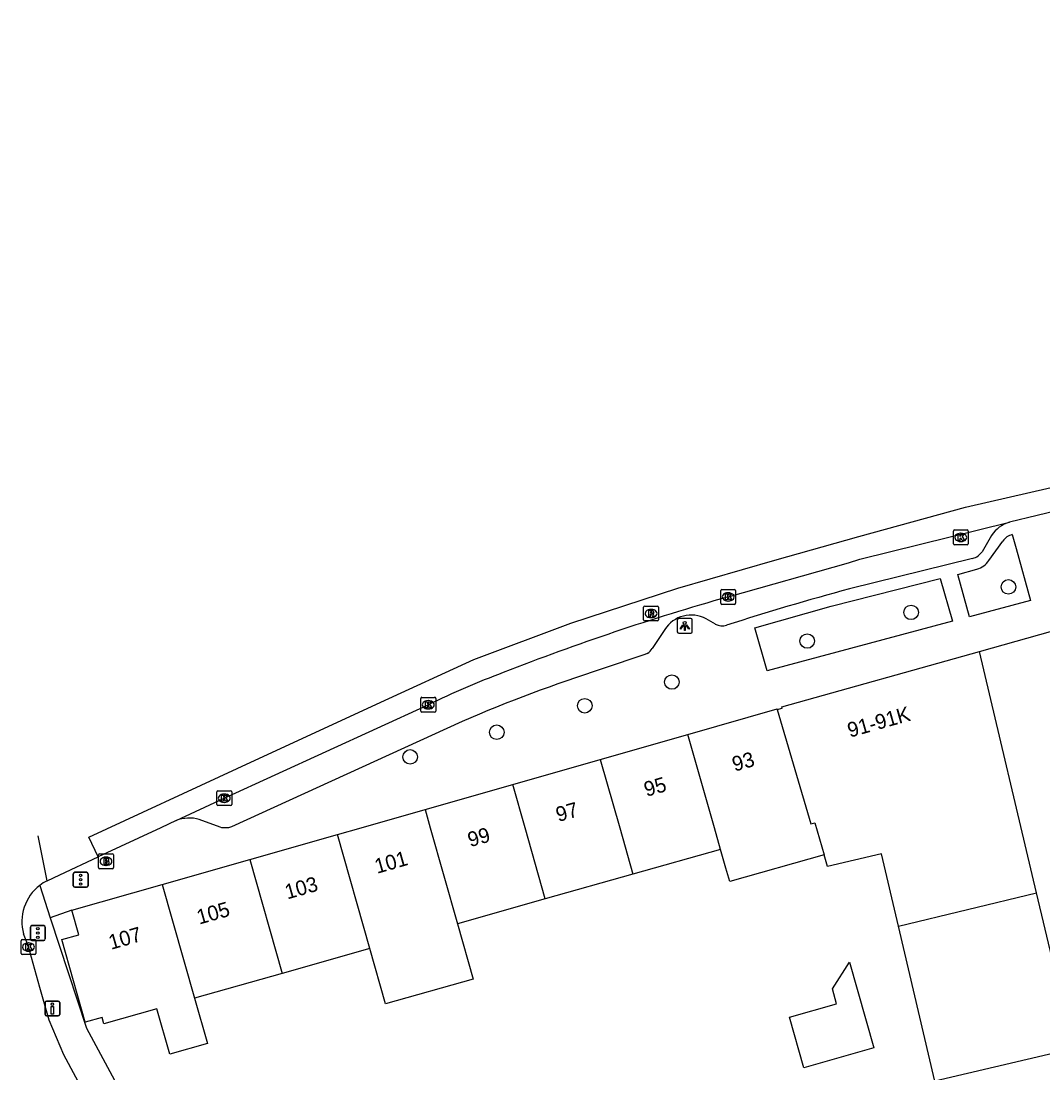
# Model space of a CAD drawing. Extents: x 159053 to 160041, y 380450 to 381422.
# Drawn here: x 159235.3 to 159304.1, y 381233.5 to 381304.3 of the extents above; entities that cross this region are included whole.
import ezdxf

# ---------------------------------------------------------------- set-up
doc = ezdxf.new("R2010")
doc.units = 0
for name, color, linetype in [('IMGEO_Boom', 7, 'Continuous'), ('IMGEO_Brandkraan', 7, 'Continuous'), ('IMGEO_Drukknoppaal', 7, 'Continuous'), ('IMGEO_Kolk', 7, 'Continuous'), ('IMGEO_Lichtpunt', 7, 'Continuous'), ('IMGEO_Muur', 7, 'Continuous'), ('IMGEO_Pand', 7, 'Continuous'), ('IMGEO_Pand_nummerreeks', 7, 'Continuous'), ('IMGEO_Rijbaan_lokaal_gesloten', 7, 'Continuous'), ('IMGEO_Rioolput', 7, 'Continuous'), ('IMGEO_Verkeersregelinstallatiepaal', 7, 'Continuous'), ('IMGEO_Voetpad_open', 7, 'Continuous')]:
    doc.layers.add(name, color=color, linetype=linetype)

msp = doc.modelspace()

# ---------------------------------------------------------------- linework, layer by layer
at = {"layer": 'IMGEO_Boom'}
for centre in [(159301.757, 381266.198), (159295.21, 381264.485), (159288.216, 381262.556), (159279.111, 381259.798), (159273.253, 381258.203), (159267.332, 381256.422), (159261.504, 381254.761)]:
    msp.add_circle(centre, 0.489, dxfattribs=at)
at = {"layer": 'IMGEO_Brandkraan'}
for p, q in [((159240.539, 381247.312), (159240.539, 381248.164)), ((159240.614, 381248.238), (159241.466, 381248.238)), ((159241.54, 381248.164), (159241.54, 381247.312)), ((159241.05, 381247.458), (159241.025, 381247.458)), ((159241.027, 381248.018), (159241.052, 381248.018)), ((159241.466, 381247.238), (159240.614, 381247.238))]:
    msp.add_line(p, q, dxfattribs=at)
for points in [[(159240.539, 381247.312), (159240.539, 381248.164)], [(159240.614, 381248.238), (159241.466, 381248.238)], [(159241.54, 381248.164), (159241.54, 381247.312)], [(159240.887, 381247.938), (159240.887, 381247.538), (159241.1, 381247.538)], [(159241.118, 381247.938), (159240.887, 381247.938)], [(159241.066, 381247.857), (159241.012, 381247.857), (159241.012, 381247.781)], [(159241.012, 381247.781), (159241.065, 381247.781)], [(159241.074, 381247.705), (159241.012, 381247.705), (159241.012, 381247.624)], [(159241.012, 381247.624), (159241.074, 381247.624)], [(159241.466, 381247.238), (159240.614, 381247.238)]]:
    msp.add_lwpolyline(points, dxfattribs=at)
for centre, radius, start, end in [((159240.616, 381248.162), 0.0765, 91.55205, 178.44795), ((159240.616, 381248.162), 0.0765, 91.55205, 178.44795), ((159241.464, 381248.162), 0.0765, 1.55205, 88.44795), ((159241.464, 381248.162), 0.0765, 1.55205, 88.44795), ((159241.067, 381247.819), 0.0379, 267.82845, 90.93552), ((159241.075, 381247.664), 0.0404, 269.87594, 90.50774), ((159241.106, 381247.789), 0.251, 268.66757, 293.53466), ((159241.122, 381247.793), 0.145, 59.4692, 91.53667), ((159241.147, 381247.84), 0.0922, 285.51372, 58.15012), ((159241.152, 381247.648), 0.105, 301.31148, 78.98903), ((159240.616, 381247.314), 0.0765, 181.55205, 268.44795), ((159240.616, 381247.314), 0.0765, 181.55205, 268.44795), ((159241.464, 381247.314), 0.0765, 271.55205, 358.44795), ((159241.464, 381247.314), 0.0765, 271.55205, 358.44795)]:
    msp.add_arc(centre, radius, start, end, dxfattribs=at)
for centre, major_axis, ratio, start_param, end_param in [((159241.026, 381247.738), (-0.387, 0.002), 0.722429, 4.712389, 7.853982), ((159241.051, 381247.738), (-0.39, 0.002), 0.717154, 1.570796, 4.712389)]:
    msp.add_ellipse(centre, major_axis=major_axis, ratio=ratio, start_param=start_param, end_param=end_param, dxfattribs=at)
at = {"layer": 'IMGEO_Drukknoppaal'}
for p, q in [((159237.036, 381238.339), (159237.826, 381238.339)), ((159237.826, 381238.339), (159237.036, 381238.339)), ((159236.936, 381237.439), (159236.936, 381238.239)), ((159236.936, 381238.239), (159236.936, 381237.439)), ((159237.926, 381238.239), (159237.926, 381237.439)), ((159237.926, 381237.439), (159237.926, 381238.239)), ((159237.826, 381237.339), (159237.036, 381237.339)), ((159237.036, 381237.339), (159237.826, 381237.339))]:
    msp.add_line(p, q, dxfattribs=at)
msp.add_lwpolyline([(159237.506, 381237.964), (159237.506, 381237.464), (159237.356, 381237.464), (159237.356, 381237.964), (159237.506, 381237.964)], dxfattribs=at)
msp.add_circle((159237.431, 381238.129), 0.085, dxfattribs=at)
for centre, start, end in [((159237.036, 381238.239), 90, 180), ((159237.036, 381238.239), 90, 180), ((159237.826, 381238.239), 0, 90), ((159237.826, 381238.239), 360, 90), ((159237.036, 381237.439), 180, 270), ((159237.036, 381237.439), 180, 270), ((159237.826, 381237.439), 270, 0), ((159237.826, 381237.439), 270, 0)]:
    msp.add_arc(centre, 0.1, start, end, dxfattribs=at)
at = {"layer": 'IMGEO_Kolk'}
for p, q in [((159298.05, 381269.104), (159298.05, 381269.956)), ((159298.125, 381270.03), (159298.977, 381270.03)), ((159298.538, 381269.81), (159298.563, 381269.81)), ((159299.051, 381269.956), (159299.051, 381269.104)), ((159298.977, 381269.03), (159298.125, 381269.03)), ((159298.561, 381269.25), (159298.536, 381269.25)), ((159282.403, 381265.098), (159282.403, 381265.95)), ((159282.478, 381266.024), (159283.33, 381266.024)), ((159283.404, 381265.95), (159283.404, 381265.098)), ((159282.914, 381265.244), (159282.889, 381265.244)), ((159282.891, 381265.804), (159282.916, 381265.804)), ((159283.33, 381265.024), (159282.478, 381265.024)), ((159262.298, 381258.769), (159263.15, 381258.769)), ((159262.223, 381257.843), (159262.223, 381258.695)), ((159262.711, 381258.549), (159262.736, 381258.549)), ((159263.224, 381258.695), (159263.224, 381257.843)), ((159263.15, 381257.769), (159262.298, 381257.769)), ((159262.734, 381257.989), (159262.709, 381257.989)), ((159248.497, 381251.559), (159248.497, 381252.411)), ((159248.572, 381252.485), (159249.424, 381252.485)), ((159249.498, 381252.411), (159249.498, 381251.559)), ((159249.008, 381251.705), (159248.983, 381251.705)), ((159248.985, 381252.265), (159249.01, 381252.265)), ((159249.424, 381251.485), (159248.572, 381251.485)), ((159235.323, 381241.544), (159235.323, 381242.396)), ((159235.398, 381242.47), (159236.25, 381242.47)), ((159235.811, 381242.25), (159235.836, 381242.25)), ((159236.324, 381242.396), (159236.324, 381241.544)), ((159236.25, 381241.47), (159235.398, 381241.47)), ((159235.834, 381241.69), (159235.809, 381241.69))]:
    msp.add_line(p, q, dxfattribs=at)
for points in [[(159298.05, 381269.104), (159298.05, 381269.956)], [(159298.125, 381270.03), (159298.977, 381270.03)], [(159298.371, 381269.73), (159298.494, 381269.73), (159298.494, 381269.579), (159298.624, 381269.73), (159298.788, 381269.73), (159298.642, 381269.579), (159298.795, 381269.33), (159298.643, 381269.33), (159298.558, 381269.494), (159298.494, 381269.427), (159298.494, 381269.33), (159298.371, 381269.33), (159298.371, 381269.73)], [(159299.051, 381269.956), (159299.051, 381269.104)], [(159298.977, 381269.03), (159298.125, 381269.03)], [(159282.403, 381265.098), (159282.403, 381265.95)], [(159282.478, 381266.024), (159283.33, 381266.024)], [(159283.404, 381265.95), (159283.404, 381265.098)], [(159282.724, 381265.724), (159282.847, 381265.724), (159282.847, 381265.573), (159282.977, 381265.724), (159283.141, 381265.724), (159282.995, 381265.573), (159283.148, 381265.324), (159282.996, 381265.324), (159282.911, 381265.488), (159282.847, 381265.421), (159282.847, 381265.324), (159282.724, 381265.324), (159282.724, 381265.724)], [(159283.33, 381265.024), (159282.478, 381265.024)], [(159262.298, 381258.769), (159263.15, 381258.769)], [(159262.223, 381257.843), (159262.223, 381258.695)], [(159262.544, 381258.469), (159262.667, 381258.469), (159262.667, 381258.318), (159262.797, 381258.469), (159262.961, 381258.469), (159262.815, 381258.318), (159262.968, 381258.069), (159262.816, 381258.069), (159262.731, 381258.233), (159262.667, 381258.166), (159262.667, 381258.069), (159262.544, 381258.069), (159262.544, 381258.469)], [(159263.224, 381258.695), (159263.224, 381257.843)], [(159263.15, 381257.769), (159262.298, 381257.769)], [(159248.497, 381251.559), (159248.497, 381252.411)], [(159248.572, 381252.485), (159249.424, 381252.485)], [(159249.498, 381252.411), (159249.498, 381251.559)], [(159248.818, 381252.185), (159248.941, 381252.185), (159248.941, 381252.034), (159249.071, 381252.185), (159249.235, 381252.185), (159249.089, 381252.034), (159249.242, 381251.785), (159249.09, 381251.785), (159249.005, 381251.949), (159248.941, 381251.882), (159248.941, 381251.785), (159248.818, 381251.785), (159248.818, 381252.185)], [(159249.424, 381251.485), (159248.572, 381251.485)], [(159235.323, 381241.544), (159235.323, 381242.396)], [(159235.398, 381242.47), (159236.25, 381242.47)], [(159235.644, 381242.17), (159235.767, 381242.17), (159235.767, 381242.019), (159235.897, 381242.17), (159236.061, 381242.17), (159235.915, 381242.019), (159236.068, 381241.77), (159235.916, 381241.77), (159235.831, 381241.934), (159235.767, 381241.867), (159235.767, 381241.77), (159235.644, 381241.77), (159235.644, 381242.17)], [(159236.324, 381242.396), (159236.324, 381241.544)], [(159236.25, 381241.47), (159235.398, 381241.47)]]:
    msp.add_lwpolyline(points, dxfattribs=at)
for centre, start, end in [((159298.127, 381269.954), 91.55205, 178.44795), ((159298.127, 381269.954), 91.55205, 178.44795), ((159298.975, 381269.954), 1.55205, 88.44795), ((159298.975, 381269.954), 1.55205, 88.44795), ((159298.127, 381269.106), 181.55205, 268.44795), ((159298.127, 381269.106), 181.55205, 268.44795), ((159298.975, 381269.106), 271.55205, 358.44795), ((159298.975, 381269.106), 271.55205, 358.44795), ((159282.48, 381265.948), 91.55205, 178.44795), ((159282.48, 381265.948), 91.55205, 178.44795), ((159283.328, 381265.948), 1.55205, 88.44795), ((159283.328, 381265.948), 1.55205, 88.44795), ((159282.48, 381265.1), 181.55205, 268.44795), ((159282.48, 381265.1), 181.55205, 268.44795), ((159283.328, 381265.1), 271.55205, 358.44795), ((159283.328, 381265.1), 271.55205, 358.44795), ((159262.3, 381258.693), 91.55205, 178.44795), ((159262.3, 381258.693), 91.55205, 178.44795), ((159263.148, 381258.693), 1.55205, 88.44795), ((159263.148, 381258.693), 1.55205, 88.44795), ((159262.3, 381257.845), 181.55205, 268.44795), ((159262.3, 381257.845), 181.55205, 268.44795), ((159263.148, 381257.845), 271.55205, 358.44795), ((159263.148, 381257.845), 271.55205, 358.44795), ((159248.574, 381252.409), 91.55205, 178.44795), ((159248.574, 381252.409), 91.55205, 178.44795), ((159249.422, 381252.409), 1.55205, 88.44795), ((159249.422, 381252.409), 1.55205, 88.44795), ((159248.574, 381251.561), 181.55205, 268.44795), ((159248.574, 381251.561), 181.55205, 268.44795), ((159249.422, 381251.561), 271.55205, 358.44795), ((159249.422, 381251.561), 271.55205, 358.44795), ((159235.4, 381242.394), 91.55205, 178.44795), ((159235.4, 381242.394), 91.55205, 178.44795), ((159236.248, 381242.394), 1.55205, 88.44795), ((159236.248, 381242.394), 1.55205, 88.44795), ((159235.4, 381241.546), 181.55205, 268.44795), ((159235.4, 381241.546), 181.55205, 268.44795), ((159236.248, 381241.546), 271.55205, 358.44795), ((159236.248, 381241.546), 271.55205, 358.44795)]:
    msp.add_arc(centre, 0.0765, start, end, dxfattribs=at)
for centre, major_axis, ratio, start_param, end_param in [((159298.537, 381269.53), (-0.387, 0.002), 0.722429, 4.712389, 7.853982), ((159298.562, 381269.53), (-0.39, 0.002), 0.717154, 1.570796, 4.712389), ((159282.89, 381265.524), (-0.387, 0.002), 0.722429, 4.712389, 7.853982), ((159282.915, 381265.524), (-0.39, 0.002), 0.717154, 1.570796, 4.712389), ((159262.71, 381258.269), (-0.387, 0.002), 0.722429, 4.712389, 7.853982), ((159262.735, 381258.269), (-0.39, 0.002), 0.717154, 1.570796, 4.712389), ((159248.984, 381251.985), (-0.387, 0.002), 0.722429, 4.712389, 7.853982), ((159249.009, 381251.985), (-0.39, 0.002), 0.717154, 1.570796, 4.712389), ((159235.81, 381241.97), (-0.387, 0.002), 0.722429, 4.712389, 7.853982), ((159235.835, 381241.97), (-0.39, 0.002), 0.717154, 1.570796, 4.712389)]:
    msp.add_ellipse(centre, major_axis=major_axis, ratio=ratio, start_param=start_param, end_param=end_param, dxfattribs=at)
at = {"layer": 'IMGEO_Lichtpunt'}
for p, q in [((159279.477, 381263.979), (159279.477, 381263.172)), ((159279.477, 381263.979), (159279.477, 381263.172)), ((159280.379, 381264.074), (159279.571, 381264.074)), ((159280.379, 381264.074), (159279.571, 381264.074)), ((159280.473, 381263.172), (159280.473, 381263.979)), ((159280.473, 381263.172), (159280.473, 381263.979)), ((159279.571, 381263.078), (159280.379, 381263.078)), ((159279.571, 381263.078), (159280.379, 381263.078))]:
    msp.add_line(p, q, dxfattribs=at)
for points in [[(159279.851, 381263.643), (159279.89, 381263.615), (159279.702, 381263.353), (159279.664, 381263.38), (159279.851, 381263.643)], [(159279.953, 381263.595), (159280, 381263.595), (159280, 381263.273), (159279.953, 381263.273), (159279.953, 381263.595)], [(159280.063, 381263.615), (159280.101, 381263.642), (159280.288, 381263.38), (159280.249, 381263.352), (159280.063, 381263.615)]]:
    msp.add_lwpolyline(points, dxfattribs=at)
msp.add_circle((159279.976, 381263.777), 0.0994, dxfattribs=at)
for centre, start, end in [((159279.571, 381263.979), 90, 180), ((159279.571, 381263.979), 90, 180), ((159280.379, 381263.979), 0, 90), ((159280.379, 381263.979), 0, 90), ((159279.571, 381263.172), 180, 270), ((159279.571, 381263.172), 180, 270), ((159280.379, 381263.172), 270, 0), ((159280.379, 381263.172), 270, 360)]:
    msp.add_arc(centre, 0.0946, start, end, dxfattribs=at)
at = {"layer": 'IMGEO_Muur'}
for points in [[(159238.752, 381244.441), (159237.275, 381243.932)], [(159237.275, 381243.932), (159239.731, 381236.517), (159243.948, 381228.686), (159245.372, 381228.997)]]:
    msp.add_lwpolyline(points, dxfattribs=at)
at = {"layer": 'IMGEO_Pand'}
for points in [[(159286.201, 381257.953), (159286.529, 381258.045), (159286.502, 381258.141), (159299.807, 381261.863)], [(159303.648, 381245.607), (159299.807, 381261.863)], [(159280.191, 381256.28), (159286.189, 381257.994), (159286.201, 381257.953)], [(159286.201, 381257.953), (159288.461, 381250.257), (159288.726, 381250.332), (159289.352, 381248.183)], [(159274.298, 381254.597), (159280.191, 381256.28)], [(159282.391, 381248.54), (159281.976, 381250), (159280.191, 381256.28)], [(159268.403, 381252.912), (159274.298, 381254.597)], [(159274.298, 381254.597), (159275.604, 381250), (159276.492, 381246.872)], [(159262.509, 381251.229), (159268.403, 381252.912)], [(159270.594, 381245.204), (159269.231, 381250), (159268.403, 381252.912)], [(159256.615, 381249.545), (159258.209, 381250), (159262.509, 381251.229)], [(159262.509, 381251.229), (159262.858, 381250), (159264.695, 381243.536)], [(159250.72, 381247.86), (159256.615, 381249.545)], [(159258.797, 381241.868), (159256.615, 381249.545)], [(159282.391, 381248.54), (159276.492, 381246.872)], [(159289.352, 381248.183), (159283.007, 381246.377), (159282.751, 381247.275), (159282.391, 381248.54)], [(159294.359, 381243.365), (159293.212, 381248.249), (159289.581, 381247.396), (159289.352, 381248.183)], [(159244.826, 381246.176), (159250.72, 381247.86)], [(159250.72, 381247.86), (159252.897, 381240.199)], [(159276.492, 381246.872), (159270.594, 381245.204)], [(159238.752, 381244.441), (159244.826, 381246.176)], [(159244.826, 381246.176), (159246.999, 381238.531)], [(159294.359, 381243.365), (159303.648, 381245.607)], [(159317.704, 381243.763), (159304.801, 381240.729), (159303.648, 381245.607)], [(159270.594, 381245.204), (159264.695, 381243.536)], [(159246.999, 381238.531), (159247.858, 381235.481), (159245.327, 381234.765), (159244.464, 381237.815), (159240.903, 381236.808), (159240.781, 381237.239), (159239.637, 381236.917), (159238.07, 381242.476), (159239.215, 381242.798), (159238.752, 381244.441)], [(159264.695, 381243.536), (159265.751, 381239.82), (159259.855, 381238.145), (159258.797, 381241.868)], [(159319.072, 381238.181), (159296.805, 381232.95), (159294.359, 381243.365)], [(159258.797, 381241.868), (159252.897, 381240.199)], [(159290.199, 381238.152), (159289.914, 381239.152), (159291.071, 381240.944), (159292.711, 381235.181), (159287.992, 381233.839), (159287.022, 381237.248), (159290.199, 381238.152)], [(159252.897, 381240.199), (159246.999, 381238.531)]]:
    msp.add_lwpolyline(points, dxfattribs=at)
at = {"layer": 'IMGEO_Rijbaan_lokaal_gesloten'}
for points in [[(159240.511, 381248.03), (159239.894, 381249.365), (159249.857, 381253.978), (159259.538, 381258.444), (159265.788, 381261.312), (159272.321, 381263.757), (159279.511, 381266.107), (159286.044, 381267.988), (159291.683, 381269.587), (159298.874, 381271.561), (159312.832, 381274.758), (159333.98, 381279.647), (159349.677, 381283.267), (159365.28, 381286.417), (159378.533, 381288.955), (159392.632, 381291.353), (159430.464, 381297.936), (159461.669, 381303.342), (159467.508, 381304.266)], [(159324.077, 381275.807), (159323.869, 381275.756), (159314.091, 381273.487), (159309.275, 381272.339), (159301.823, 381270.543)], [(159282.899, 381265.526), (159290.99, 381267.825), (159291.758, 381268.073), (159301.823, 381270.543)], [(159245.754, 381250.48), (159248.994, 381251.986), (159262.72, 381258.27)], [(159245.754, 381250.48), (159244.727, 381250), (159240.511, 381248.03)], [(159237.075, 381246.424), (159236.466, 381249.451)], [(159237.075, 381246.424), (159237.944, 381246.83), (159240.511, 381248.03)], [(159240.3, 381230.796), (159238.2, 381234.713), (159237.21, 381237.061), (159236.582, 381239.242), (159235.793, 381242.082), (159235.5, 381242.849)]]:
    msp.add_lwpolyline(points, dxfattribs=at)
for centre, radius, start, end in [((159327.171, 381108.902), 162.76, 105.78358, 111.40419), ((159287.846, 381206.666), 57.395, 110.47153, 115.96124), ((159238.435, 381243.69), 3.054, 127.39543, 195.9874), ((159238.438, 381243.687), 3.058, 116.48007, 127.40551)]:
    msp.add_arc(centre, radius, start, end, dxfattribs=at)
at = {"layer": 'IMGEO_Rioolput'}
for p, q in [((159277.214, 381263.983), (159277.214, 381264.835)), ((159277.289, 381264.909), (159278.141, 381264.909)), ((159277.702, 381264.689), (159277.727, 381264.689)), ((159278.215, 381264.835), (159278.215, 381263.983)), ((159278.141, 381263.909), (159277.289, 381263.909)), ((159277.725, 381264.129), (159277.7, 381264.129))]:
    msp.add_line(p, q, dxfattribs=at)
for points in [[(159277.214, 381263.983), (159277.214, 381264.835)], [(159277.289, 381264.909), (159278.141, 381264.909)], [(159277.803, 381264.607), (159277.551, 381264.609), (159277.551, 381264.209)], [(159277.729, 381264.528), (159277.675, 381264.528), (159277.675, 381264.447)], [(159277.675, 381264.447), (159277.727, 381264.447)], [(159278.215, 381264.835), (159278.215, 381263.983)], [(159278.141, 381263.909), (159277.289, 381263.909)], [(159277.551, 381264.209), (159277.675, 381264.209), (159277.675, 381264.371), (159277.686, 381264.371)], [(159277.733, 381264.342), (159277.804, 381264.209), (159277.944, 381264.209), (159277.879, 381264.335)]]:
    msp.add_lwpolyline(points, dxfattribs=at)
for centre, radius, start, end in [((159277.291, 381264.833), 0.0765, 91.55205, 178.44795), ((159277.291, 381264.833), 0.0765, 91.55205, 178.44795), ((159277.711, 381264.636), 0.19, 274.7715, 282.96867), ((159277.735, 381264.432), 0.0964, 77.00612, 93.18647), ((159277.749, 381264.489), 0.0378, 276.66336, 79.67722), ((159277.802, 381264.497), 0.109, 350.36119, 89.41601), ((159277.8, 381264.497), 0.112, 277.58423, 350.98172), ((159278.139, 381264.833), 0.0765, 1.55205, 88.44795), ((159278.139, 381264.833), 0.0765, 1.55205, 88.44795), ((159277.291, 381263.985), 0.0765, 181.55205, 268.44795), ((159277.291, 381263.985), 0.0765, 181.55205, 268.44795), ((159277.685, 381264.318), 0.0533, 26.02933, 88.69889), ((159277.784, 381264.282), 0.108, 29.51342, 73.79051), ((159278.139, 381263.985), 0.0765, 271.55205, 358.44795), ((159278.139, 381263.985), 0.0765, 271.55205, 358.44795)]:
    msp.add_arc(centre, radius, start, end, dxfattribs=at)
for centre, major_axis, ratio, start_param, end_param in [((159277.701, 381264.409), (-0.387, 0.002), 0.722429, 4.712389, 7.853982), ((159277.726, 381264.409), (-0.39, 0.002), 0.717154, 1.570796, 4.712389)]:
    msp.add_ellipse(centre, major_axis=major_axis, ratio=ratio, start_param=start_param, end_param=end_param, dxfattribs=at)
at = {"layer": 'IMGEO_Verkeersregelinstallatiepaal'}
for p, q in [((159238.839, 381246.099), (159238.839, 381246.899)), ((159238.839, 381246.899), (159238.839, 381246.099)), ((159238.939, 381246.999), (159239.729, 381246.999)), ((159239.729, 381246.999), (159238.939, 381246.999)), ((159239.829, 381246.899), (159239.829, 381246.099)), ((159239.829, 381246.099), (159239.829, 381246.899)), ((159239.729, 381245.999), (159238.939, 381245.999)), ((159238.939, 381245.999), (159239.729, 381245.999)), ((159235.96, 381242.513), (159235.96, 381243.313)), ((159235.96, 381243.313), (159235.96, 381242.513)), ((159236.06, 381243.413), (159236.85, 381243.413)), ((159236.85, 381243.413), (159236.06, 381243.413)), ((159236.95, 381243.313), (159236.95, 381242.513)), ((159236.95, 381242.513), (159236.95, 381243.313)), ((159236.85, 381242.413), (159236.06, 381242.413)), ((159236.06, 381242.413), (159236.85, 381242.413))]:
    msp.add_line(p, q, dxfattribs=at)
for centre in [(159239.334, 381246.789), (159239.334, 381246.499), (159239.334, 381246.209), (159236.455, 381243.203), (159236.455, 381242.913), (159236.455, 381242.623)]:
    msp.add_circle(centre, 0.085, dxfattribs=at)
for centre, start, end in [((159238.939, 381246.899), 90, 180), ((159238.939, 381246.899), 90, 180), ((159239.729, 381246.899), 0, 90), ((159239.729, 381246.899), 360, 90), ((159238.939, 381246.099), 180, 270), ((159238.939, 381246.099), 180, 270), ((159239.729, 381246.099), 270, 0), ((159239.729, 381246.099), 270, 0), ((159236.06, 381243.313), 90, 180), ((159236.06, 381243.313), 90, 180), ((159236.85, 381243.313), 0, 90), ((159236.85, 381243.313), 360, 90), ((159236.06, 381242.513), 180, 270), ((159236.06, 381242.513), 180, 270), ((159236.85, 381242.513), 270, 0), ((159236.85, 381242.513), 270, 0)]:
    msp.add_arc(centre, 0.1, start, end, dxfattribs=at)
at = {"layer": 'IMGEO_Voetpad_open'}
for points in [[(159300.625, 381269.656), (159299.996, 381268.567)], [(159302.012, 381269.713), (159302.28, 381268.784), (159303.231, 381265.279)], [(159300.433, 381267.984), (159301.386, 381269.278)], [(159299.347, 381268.115), (159291.073, 381266.064)], [(159303.231, 381265.279), (159299.148, 381264.191), (159298.353, 381267.038), (159299.633, 381267.398)], [(159285.526, 381260.56), (159284.7, 381263.444), (159289.829, 381264.913), (159297.174, 381266.762), (159297.99, 381263.895), (159285.526, 381260.56)], [(159299.807, 381261.863), (159307.925, 381264.149), (159313.719, 381265.781), (159316.137, 381266.263)], [(159282.037, 381263.698), (159281.419, 381264.051)], [(159278.635, 381263.328), (159277.791, 381262.061)], [(159277.454, 381261.718), (159277.287, 381261.641), (159274.424, 381260.688)], [(159264.999, 381257.142), (159249.492, 381250.063), (159249.28, 381250), (159248.84, 381250), (159248.724, 381250.029), (159247.319, 381250.551)], [(159236.581, 381246.116), (159237.275, 381243.932)], [(159238.752, 381244.441), (159237.275, 381243.932)], [(159237.275, 381243.932), (159239.731, 381236.517), (159243.948, 381228.686), (159245.372, 381228.997)]]:
    msp.add_lwpolyline(points, dxfattribs=at)
for centre, radius, start, end in [((159302.365, 381268.559), 2.057, 105.26839, 147.76416), ((159302.22, 381268.746), 0.99, 102.14204, 147.44792), ((159299.025, 381269.269), 1.198, 285.58468, 324.12635), ((159299.366, 381268.601), 1.232, 282.49788, 329.94767), ((159333.969, 381105.684), 166.018, 104.97419, 107.95538), ((159280.415, 381262.197), 2.109, 61.55314, 147.5629), ((159282.523, 381264.665), 1.083, 243.30635, 284.26387), ((159276.971, 381262.53), 0.944, 300.75617, 330.25491), ((159306.662, 381160.703), 105.053, 107.87085, 113.3651), ((159246.642, 381248.197), 2.45, 73.94827, 111.24689)]:
    msp.add_arc(centre, radius, start, end, dxfattribs=at)

# ---------------------------------------------------------------- texts
at = {"layer": 'IMGEO_Pand_nummerreeks'}
for s, rotation, p in [('91-91K', 15.7105, (159291.09, 381256.053)), ('93', 15.94542, (159283.331, 381253.766)), ('95', 15.94542, (159277.401, 381252.071)), ('97', 15.94492, (159271.472, 381250.377)), ('99', 15.94492, (159265.542, 381248.683)), ('101', 15.94492, (159259.278, 381246.894)), ('103', 15.94492, (159253.239, 381245.169)), ('105', 15.94492, (159247.309, 381243.475)), ('107', 15.94542, (159241.379, 381241.781))]:
    msp.add_text(s, height=1, rotation=rotation, dxfattribs=at).set_placement(p)

doc.saveas('drawing.dxf')
